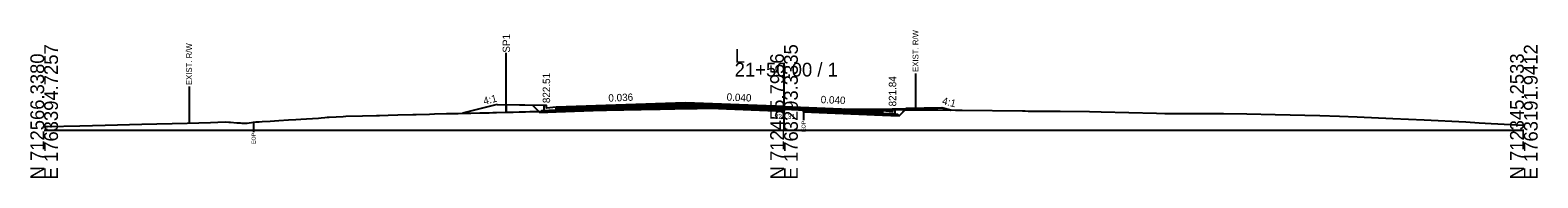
# Model space of a CAD drawing. Extents: x -26 to 5303, y -10 to 9578.
# Drawn here: x 997.2 to 1302.8, y 1490.3 to 1520.4 of the extents above; entities that cross this region are included whole.
import ezdxf

# ---------------------------------------------------------------- set-up
doc = ezdxf.new("R2010")
doc.units = 0
for name, color, linetype in [('Default', 7, 'Continuous'), ('Exist CMT Pavement', 7, 'Continuous'), ('Exist Cross Section Cell', 7, 'Continuous'), ('Exist XS Ground Line', 7, 'Continuous'), ('Old_Level_10', 7, 'Continuous'), ('Old_Level_3', 7, 'Continuous'), ('Prop CMT Conc Surface', 7, 'Continuous'), ('Prop CMT Concrete Structures', 7, 'Continuous'), ('Prop CMT Pvmt Course 1', 7, 'Continuous'), ('Prop CMT Pvmt Course 1 CG', 7, 'Continuous'), ('Prop CMT Pvmt Course 2', 7, 'Continuous'), ('Prop CMT Pvmt Course 3', 7, 'Continuous'), ('Prop CMT Pvmt Surface', 7, 'Continuous'), ('Prop CMT Slope Grass', 7, 'Continuous'), ('Prop CMT Subgrade Earthwork', 7, 'Continuous'), ('Prop XS Earthwork Shape', 7, 'Continuous'), ('Prop XS Hydro Elevations', 7, 'Continuous'), ('Prop XS SE Text', 7, 'Continuous'), ('Prop XS Shear Point Element', 7, 'Continuous'), ('Prop XS Side Slope Text', 7, 'Continuous'), ('Prop XS Wedging', 7, 'Continuous'), ('Scratch_Level_0', 7, 'Continuous')]:
    doc.layers.add(name, color=color, linetype=linetype)

msp = doc.modelspace()

# ---------------------------------------------------------------- linework, layer by layer
at = {"layer": 'Exist CMT Pavement'}
msp.add_lwpolyline([(1150, 1504.32), (1151.15, 1504.27), (1152.97, 1504.17), (1153.97, 1504.08)], dxfattribs=at)
at = {"layer": 'Exist Cross Section Cell'}
for p, q in [((1150, 1500), (1150, 1513.72)), ((1000, 1500), (1150, 1500)), ((1150, 1500), (1300, 1500))]:
    msp.add_line(p, q, dxfattribs=at)
at = {"layer": 'Exist XS Ground Line'}
msp.add_lwpolyline([(1000, 1500.73), (1000.7, 1500.75), (1007.22, 1500.89), (1012.35, 1501.05), (1019.8, 1501.21), (1029, 1501.46), (1033.7, 1501.57), (1036.67, 1501.7), (1037.42, 1501.63), (1037.75, 1501.62), (1039.04, 1501.52), (1039.73, 1501.49), (1040.1, 1501.43), (1041.13, 1501.44), (1042.46, 1501.63), (1042.92, 1501.68), (1043.57, 1501.72), (1044.22, 1501.77), (1045.83, 1501.86), (1047.61, 1501.97), (1049.52, 1502.09), (1051, 1502.18), (1052.07, 1502.22), (1053.22, 1502.3), (1054.4, 1502.38), (1055.6, 1502.48), (1056.19, 1502.52), (1056.92, 1502.59), (1057.37, 1502.63), (1057.79, 1502.66), (1060.62, 1502.81), (1061.18, 1502.84), (1064.57, 1502.94), (1067.41, 1503.01), (1068.02, 1503.03), (1069.76, 1503.08), (1071.72, 1503.14), (1074.75, 1503.21), (1075.41, 1503.23), (1078.14, 1503.28), (1079.11, 1503.31), (1081.54, 1503.37), (1082.81, 1503.4), (1083.92, 1503.43), (1084.93, 1503.45), (1085.68, 1503.46), (1086.51, 1503.48), (1088.32, 1503.52), (1090.21, 1503.57), (1090.99, 1503.59), (1091.71, 1503.61), (1093.91, 1503.66), (1095.11, 1503.69), (1097.6, 1503.76), (1098.5, 1503.78), (1099.84, 1503.8), (1101.3, 1503.82), (1101.89, 1503.83), (1105.28, 1503.91), (1106.92, 1503.94), (1108.7, 1503.98), (1110.46, 1504.02), (1112.4, 1504.07), (1114, 1504.11), (1115.46, 1504.14), (1115.76, 1504.15), (1116.1, 1504.15), (1117.53, 1504.18), (1118.85, 1504.22), (1119.8, 1504.23), (1122.24, 1504.26), (1123.49, 1504.28), (1124.88, 1504.3), (1125.81, 1504.33), (1126.3, 1504.33), (1126.83, 1504.33), (1127.25, 1504.35), (1127.84, 1504.38), (1128.15, 1504.4), (1129.03, 1504.39), (1130.89, 1504.4), (1132.42, 1504.45), (1133.46, 1504.49), (1134.59, 1504.49), (1135.23, 1504.49), (1135.81, 1504.5), (1137, 1504.52), (1138.29, 1504.55), (1138.77, 1504.56), (1139.52, 1504.57), (1139.94, 1504.57), (1140.56, 1504.57), (1141.99, 1504.54), (1142.6, 1504.52), (1144.08, 1504.51), (1145.99, 1504.42), (1147.61, 1504.37), (1149.38, 1504.34), (1150, 1504.31), (1152.97, 1504.17), (1153.97, 1504.08), (1154.82, 1504.02), (1155.83, 1503.94), (1156.42, 1504.38), (1169.05, 1504.23), (1170.59, 1504.21), (1171.23, 1504.21), (1177.67, 1504.19), (1184.8, 1504.06), (1186.13, 1504.05), (1198.38, 1503.92), (1198.9, 1503.92), (1199.48, 1503.91), (1205.98, 1503.89), (1211.95, 1503.79), (1214.28, 1503.74), (1225.52, 1503.44), (1227.22, 1503.42), (1239.09, 1503.37), (1243.87, 1503.34), (1249.6, 1503.2), (1258.66, 1502.98), (1262.61, 1502.86), (1266.23, 1502.73), (1273.46, 1502.4), (1279.8, 1502.13), (1288.26, 1501.71), (1290.93, 1501.52), (1293.37, 1501.38), (1300, 1501.03)], dxfattribs=at)
at = {"layer": 'Old_Level_10'}
for p, q in [((1176.66, 1511.55), (1176.66, 1504.15)), ((1029.37, 1508.87), (1029.37, 1501.47)), ((1153.97, 1504.08), (1153.97, 1502.03)), ((1042.46, 1501.63), (1042.46, 1499.58))]:
    msp.add_line(p, q, dxfattribs=at)
at = {"layer": 'Prop CMT Conc Surface'}
for points in [[(1101.83, 1504.51), (1101.83, 1505.01), (1101.33, 1505.01)], [(1103.83, 1504.67), (1101.83, 1504.51)], [(1170, 1504), (1172, 1503.84)], [(1172, 1503.84), (1172, 1504.34), (1172.5, 1504.34)]]:
    msp.add_lwpolyline(points, dxfattribs=at)
at = {"layer": 'Prop CMT Concrete Structures'}
for points in [[(1103.83, 1504.67), (1101.83, 1504.51), (1101.83, 1505.01), (1101.33, 1505.01)], [(1101.33, 1505.01), (1101.33, 1503.98), (1103.83, 1504.08)], [(1103.83, 1504.08), (1103.83, 1504.67)], [(1170, 1504), (1172, 1503.84), (1172, 1504.34), (1172.5, 1504.34)], [(1172.5, 1504.34), (1172.5, 1503.32), (1170, 1503.42)], [(1170, 1503.42), (1170, 1504)]]:
    msp.add_lwpolyline(points, dxfattribs=at)
at = {"layer": 'Prop CMT Pvmt Course 1'}
for points in [[(1150, 1504.8), (1130, 1505.6)], [(1130, 1505.35), (1150, 1504.55)], [(1150, 1504.55), (1150, 1504.8)], [(1150, 1504.8), (1170, 1504)], [(1153.97, 1504.39), (1150, 1504.55)], [(1150, 1504.55), (1150, 1504.55), (1150, 1504.55)], [(1170, 1503.75), (1153.97, 1504.39)], [(1153.97, 1504.39), (1153.97, 1504.39)], [(1170, 1504), (1170, 1503.75)]]:
    msp.add_lwpolyline(points, dxfattribs=at)
msp.add_lwpolyline([(1150, 1504.55), (1150, 1504.55), (1150, 1504.55), (1150, 1504.55)], close=True, dxfattribs=at)
at = {"layer": 'Prop CMT Pvmt Course 1 CG'}
for points in [[(1103.83, 1504.08), (1100.83, 1503.96), (1100.49, 1503.62)], [(1103.83, 1503.75), (1103.83, 1504.08)], [(1100.49, 1503.62), (1103.83, 1503.75)], [(1170, 1503.42), (1173, 1503.3), (1173.35, 1502.95)], [(1170, 1503.08), (1170, 1503.42)], [(1173.35, 1502.95), (1170, 1503.08)]]:
    msp.add_lwpolyline(points, dxfattribs=at)
at = {"layer": 'Prop CMT Pvmt Course 2'}
for points in [[(1130, 1505.35), (1103.83, 1504.42)], [(1103.83, 1504.08), (1130, 1505.02)], [(1103.83, 1504.42), (1103.83, 1504.08)], [(1103.83, 1504.42), (1103.83, 1504.08)], [(1150, 1504.55), (1130, 1505.35)], [(1130, 1505.02), (1150, 1504.22)], [(1150, 1504.22), (1150, 1504.55)], [(1153.97, 1504.06), (1153.97, 1504.39)], [(1153.97, 1504.39), (1170, 1503.75)], [(1170, 1503.42), (1153.97, 1504.06)], [(1170, 1503.75), (1170, 1503.42)]]:
    msp.add_lwpolyline(points, dxfattribs=at)
at = {"layer": 'Prop CMT Pvmt Course 3'}
for points in [[(1130, 1505.02), (1103.83, 1504.08)], [(1103.83, 1503.75), (1130, 1504.68)], [(1103.83, 1504.08), (1103.83, 1503.75)], [(1103.83, 1504.08), (1103.83, 1503.75)], [(1150, 1504.22), (1130, 1505.02)], [(1130, 1504.68), (1150, 1503.88)], [(1150, 1503.88), (1150, 1504.22)], [(1153.97, 1504.06), (1170, 1503.42)], [(1153.97, 1503.73), (1153.97, 1504.06)], [(1170, 1503.08), (1153.97, 1503.73)], [(1170, 1503.42), (1170, 1503.08)]]:
    msp.add_lwpolyline(points, dxfattribs=at)
at = {"layer": 'Prop CMT Pvmt Surface'}
for points in [[(1130, 1505.6), (1103.83, 1504.67)], [(1150, 1504.8), (1130, 1505.6)], [(1150, 1504.8), (1170, 1504)]]:
    msp.add_lwpolyline(points, dxfattribs=at)
at = {"layer": 'Prop CMT Slope Grass'}
msp.add_line((1093.67, 1503.65), (1093.67, 1505.16), dxfattribs=at)
for points in [[(1101.33, 1505.01), (1093.67, 1505.16)], [(1172.5, 1504.34), (1182, 1504.53), (1183.83, 1504.07)]]:
    msp.add_lwpolyline(points, dxfattribs=at)
at = {"layer": 'Prop CMT Subgrade Earthwork'}
for p, q in [((1150, 1503.88), (1150, 1504.32)), ((1153.97, 1503.73), (1153.97, 1504.08))]:
    msp.add_line(p, q, dxfattribs=at)
for points in [[(1103.83, 1503.75), (1100.49, 1503.62), (1099.05, 1505.05)], [(1130, 1504.68), (1103.83, 1503.75)], [(1150, 1503.88), (1130, 1504.68)], [(1170, 1503.08), (1173.35, 1502.95), (1174.78, 1504.39)], [(1153.97, 1503.73), (1170, 1503.08)]]:
    msp.add_lwpolyline(points, dxfattribs=at)
at = {"layer": 'Prop XS Earthwork Shape'}
for points in [[(1100.3, 1503.81), (1099.05, 1505.05), (1093.67, 1505.16), (1093.67, 1503.66), (1093.91, 1503.66), (1094.53, 1503.67), (1095.11, 1503.69), (1096.3, 1503.73), (1097.6, 1503.76), (1098.5, 1503.78)], [(1100.3, 1503.81), (1101.3, 1503.82), (1101.89, 1503.83), (1103.38, 1503.87), (1105.28, 1503.91), (1106.92, 1503.94), (1108.7, 1503.98), (1110.46, 1504.02), (1112.4, 1504.07), (1113.75, 1504.11), (1103.83, 1503.75), (1100.49, 1503.62)], [(1113.75, 1504.11), (1115.46, 1504.14), (1116.1, 1504.15), (1118.85, 1504.22), (1119.3, 1504.23), (1119.8, 1504.23), (1121.07, 1504.24), (1122.24, 1504.26), (1122.84, 1504.27), (1123.49, 1504.28), (1124.88, 1504.3), (1125.81, 1504.33), (1126.3, 1504.33), (1126.83, 1504.33), (1127.25, 1504.35), (1127.84, 1504.38), (1128.15, 1504.4), (1129.03, 1504.39), (1129.92, 1504.4), (1130.89, 1504.4), (1132.42, 1504.45), (1133.46, 1504.49), (1134.59, 1504.49), (1134.8, 1504.49), (1130, 1504.68)], [(1134.8, 1504.49), (1135.23, 1504.49), (1135.81, 1504.5), (1138.29, 1504.55), (1138.77, 1504.56), (1139.21, 1504.56), (1139.94, 1504.57), (1140.56, 1504.57), (1141.99, 1504.54), (1142.6, 1504.52), (1144.08, 1504.51), (1145.99, 1504.42), (1147.61, 1504.37), (1149.38, 1504.34), (1150, 1504.32), (1150, 1503.88)], [(1172, 1504.2), (1174.57, 1504.17), (1173.35, 1502.95), (1170, 1503.08), (1153.97, 1503.73), (1153.97, 1504.08), (1154.82, 1504.02), (1155.83, 1503.94), (1156.42, 1504.38), (1162.18, 1504.31), (1170, 1504), (1172, 1503.84)], [(1171.23, 1504.21), (1172, 1504.2), (1172, 1503.84), (1170, 1504), (1162.18, 1504.31), (1169.05, 1504.23), (1170.59, 1504.21)], [(1170, 1504), (1172, 1503.84), (1172, 1504.2), (1171.23, 1504.21), (1170.59, 1504.21), (1169.05, 1504.23), (1162.18, 1504.31)], [(1174.57, 1504.17), (1183.83, 1504.07), (1182, 1504.53), (1174.78, 1504.39)]]:
    msp.add_lwpolyline(points, close=True, dxfattribs=at)
at = {"layer": 'Prop XS Shear Point Element'}
msp.add_line((1093.67, 1505.16), (1093.67, 1515.76), dxfattribs=at)
at = {"layer": 'Prop XS Wedging'}
for points in [[(1130, 1504.4), (1130, 1505.35), (1130.89, 1505.32), (1132.42, 1505.25), (1133.46, 1505.21), (1134.59, 1505.17), (1135.23, 1505.14), (1135.81, 1505.12), (1138.29, 1505.02), (1138.77, 1505), (1139.21, 1504.98), (1139.94, 1504.95), (1140.56, 1504.93), (1141.99, 1504.87), (1142.6, 1504.85), (1144.08, 1504.79), (1145.99, 1504.71), (1147.61, 1504.65), (1149.38, 1504.58), (1150, 1504.55), (1151.15, 1504.5), (1152.97, 1504.43), (1153.97, 1504.39), (1153.97, 1504.08), (1152.97, 1504.17), (1151.15, 1504.28), (1150, 1504.32), (1149.38, 1504.34), (1147.61, 1504.37), (1145.99, 1504.42), (1144.08, 1504.51), (1142.6, 1504.53), (1141.99, 1504.54), (1140.56, 1504.58), (1139.94, 1504.57), (1139.21, 1504.56), (1138.77, 1504.56), (1138.29, 1504.55), (1135.81, 1504.5), (1135.23, 1504.49), (1134.59, 1504.49), (1133.46, 1504.49), (1132.42, 1504.45), (1130.89, 1504.4)], [(1130, 1504.4), (1130, 1505.02), (1130.89, 1504.99), (1132.42, 1504.92), (1133.46, 1504.88), (1134.59, 1504.84), (1135.23, 1504.81), (1135.81, 1504.79), (1136.41, 1504.76), (1136.65, 1504.52), (1135.81, 1504.5), (1135.23, 1504.49), (1134.59, 1504.49), (1133.46, 1504.49), (1132.42, 1504.45), (1130.89, 1504.4)]]:
    msp.add_lwpolyline(points, close=True, dxfattribs=at)
at = {"layer": 'Scratch_Level_0'}
msp.add_line((1091.83, 1505.2), (1093.67, 1505.16), dxfattribs=at)
msp.add_lwpolyline([(1091.83, 1505.2), (1084.83, 1503.45)], dxfattribs=at)

# ---------------------------------------------------------------- texts
at = {"layer": 'Default'}
msp.add_text('-', height=0.0001, dxfattribs=at).set_placement((1000, 1500))
at = {"layer": 'Exist Cross Section Cell'}
for s, p in [('E 1763394.7257', (1002.8, 1490)), ('E 1763293.3335', (1152.8, 1490)), ('E 1763191.9412', (1302.8, 1490)), ('N 712566.3380', (1000, 1490)), ('N 712455.7956', (1150, 1490)), ('N 712345.2533', (1300, 1490))]:
    msp.add_text(s, height=2.8, rotation=90, dxfattribs=at).set_placement(p)
for s, p in [('L', (1140, 1513.72)), ('21+50.00 / 1', (1140, 1510.92))]:
    msp.add_text(s, height=2.8, dxfattribs=at).set_placement(p)
at = {"layer": 'Old_Level_10'}
for s, height, p in [('EXIST. R/W', 1.181, (1177.25, 1511.85)), ('EXIST. R/W', 1.181, (1029.96, 1509.17)), ('EOP', 0.787, (1154.36, 1499.63)), ('EOP', 0.787, (1042.86, 1497.18))]:
    msp.add_text(s, height=height, rotation=90, dxfattribs=at).set_placement(p)
at = {"layer": 'Old_Level_3'}
msp.add_text('822.31', height=1, dxfattribs=at).set_placement((1148.05, 1502.31))
at = {"layer": 'Prop XS Hydro Elevations'}
for s, p in [('822.51', (1102.58, 1505.51)), ('821.84', (1172.75, 1504.84))]:
    msp.add_text(s, height=1.5, rotation=90, dxfattribs=at).set_placement(p)
at = {"layer": 'Prop XS SE Text'}
for s, rotation, p in [('0.036', 2.2906, (1114.42, 1505.8)), ('0.040', 357.7094, (1138.35, 1506.02)), ('0.040', 357.7094, (1157.42, 1505.51))]:
    msp.add_text(s, height=1.5, rotation=rotation, dxfattribs=at).set_placement(p)
at = {"layer": 'Prop XS Shear Point Element'}
msp.add_text('SP1', height=1.5, rotation=90, dxfattribs=at).set_placement((1094.45, 1515.77))
at = {"layer": 'Prop XS Side Slope Text'}
msp.add_text('4:1', height=1.5, rotation=345.9638, dxfattribs=at).set_placement((1181.94, 1505.32))
at = {"layer": 'Scratch_Level_0'}
msp.add_text('4:1', height=1.5, rotation=14.0362, dxfattribs=at).set_placement((1089.23, 1505.17))

doc.saveas('drawing.dxf')
